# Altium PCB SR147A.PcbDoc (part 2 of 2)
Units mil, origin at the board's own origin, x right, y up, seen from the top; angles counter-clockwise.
Board outline 3000 x 3006 mil, 4 copper layers (Top Layer, Signal Layer 1, Signal Layer 2, Bottom Layer), stack 60.434 mil thick; 65 components, 14 nets, 93 pads, 851 vias.
Unrouted connection lines stored in the file: 2.
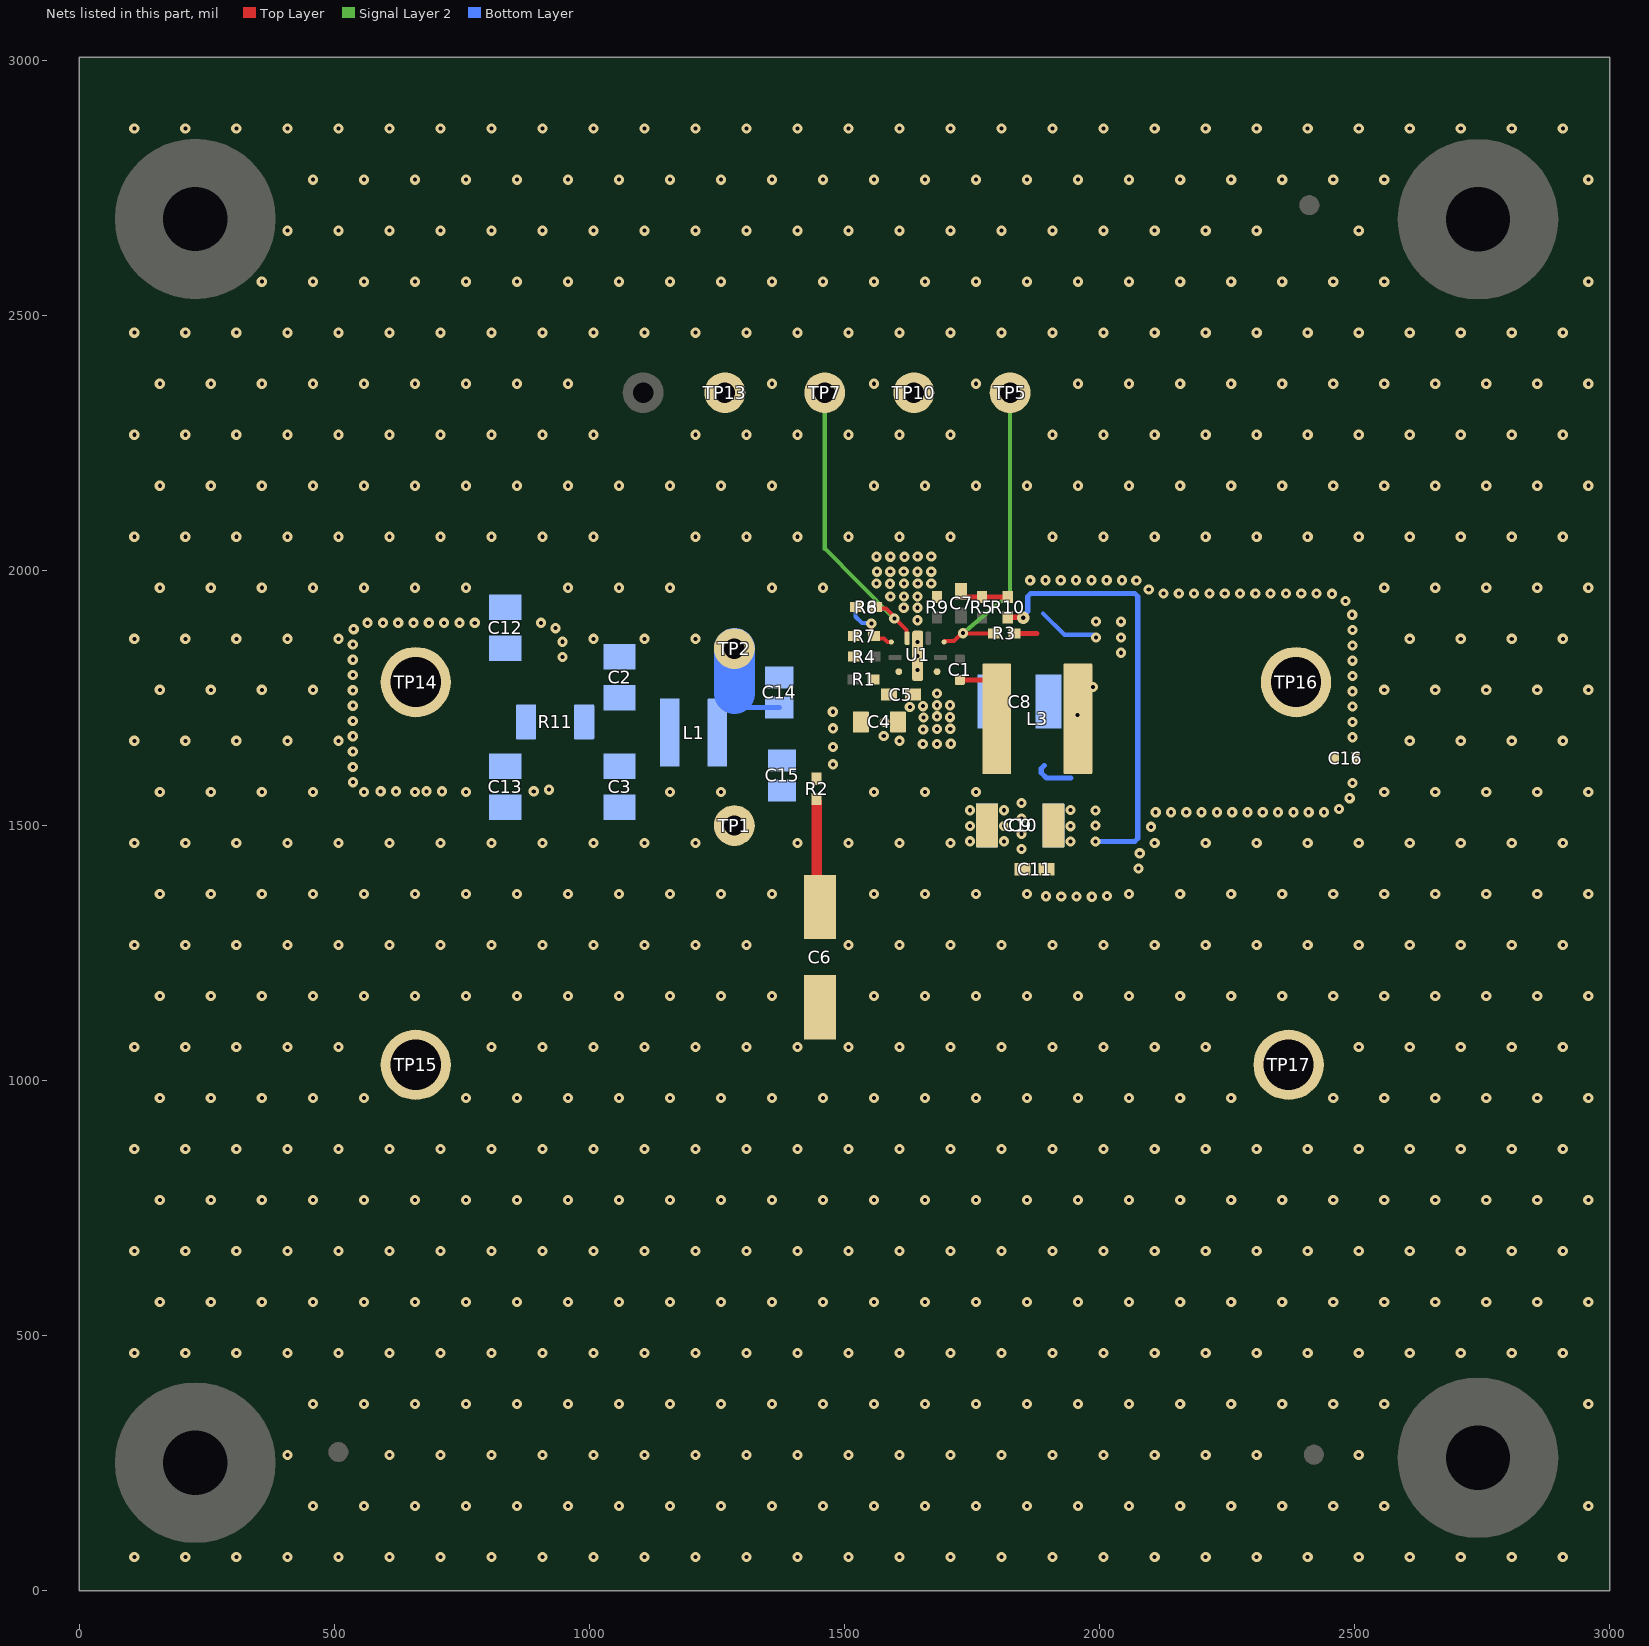
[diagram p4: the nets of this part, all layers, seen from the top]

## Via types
v1: diameter 20, hole 8, Top Layer to Bottom Layer, tented both sides, 847 vias
v2: diameter 19.68, hole 7.87, Top Layer to Bottom Layer, tented both sides, 3 vias
v3: diameter 24, hole 8, Top Layer to Bottom Layer, tented both sides, 1 vias

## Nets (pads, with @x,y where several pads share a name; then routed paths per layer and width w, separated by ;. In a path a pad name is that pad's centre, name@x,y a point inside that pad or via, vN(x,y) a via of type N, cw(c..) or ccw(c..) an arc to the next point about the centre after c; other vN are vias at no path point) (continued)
GND: C2.2 C3.2 C4.1 C5.2 C6.2 C8.2 C9.1 C10.1 C11.2 C12.2 C13.2 C14.2 C15.2 C16.2 R4.1 R7.1 R8.1 R9.1 TP1.1 TP10.1 TP13.1 TP15.1 TP17.1 U1.2
  other v1: 108,66 208,66 308,66 408,66 508,66 608,66 708,66 808,66 908,66 1008,66 1108,66 1208,66 1308,66 1408,66 1508,66 1608,66 1708,66 1808,66 1908,66 2008,66 2108,66 2208,66 2308,66 2408,66 2508,66 2608,66 2708,66 2808,66 2908,66 458,166 558,166 658,166 758,166 858,166 958,166 1058,166 1158,166 1258,166 1358,166 1458,166 1558,166 1658,166 1758,166 1858,166 1958,166 2058,166 2158,166 2258,166 2358,166 2458,166 2558,166 2958,166 408,266 608,266 708,266 808,266 908,266 1008,266 1108,266 1208,266 1308,266 1408,266 1508,266 1608,266 1708,266 1808,266 1908,266 2008,266 2108,266 2208,266 2308,266 2508,266 458,366 558,366 658,366 758,366 858,366 958,366 1058,366 1158,366 1258,366 1358,366 1458,366 1558,366 1658,366 1758,366 1858,366 1958,366 2058,366 2158,366 2258,366 2358,366 2458,366 2558,366 2958,366 108,466 208,466 308,466 408,466 508,466 608,466 708,466 808,466 908,466 1008,466 1108,466 1208,466 1308,466 1408,466 1508,466 1608,466 1708,466 1808,466 1908,466 2008,466 2108,466 2208,466 2308,466 2408,466 2508,466 2608,466 2708,466 2808,466 2908,466 158,566 258,566 358,566 458,566 558,566 658,566 758,566 858,566 958,566 1058,566 1158,566 1258,566 1358,566 1458,566 1558,566 1658,566 1758,566 1858,566 1958,566 2058,566 2158,566 2258,566 2358,566 2458,566 2558,566 2658,566 2758,566 2858,566 2958,566 108,666 208,666 308,666 408,666 508,666 608,666 708,666 808,666 908,666 1008,666 1108,666 1208,666 1308,666 1408,666 1508,666 1608,666 1708,666 1808,666 1908,666 2008,666 2108,666 2208,666 2308,666 2408,666 2508,666 2608,666 2708,666 2808,666 2908,666 158,766 258,766 358,766 458,766 558,766 658,766 758,766 858,766 958,766 1058,766 1158,766 1258,766 1358,766 1458,766 1558,766 1658,766 1758,766 1858,766 1958,766 2058,766 2158,766 2258,766 2358,766 2458,766 2558,766 2658,766 2758,766 2858,766 2958,766 108,866 208,866 308,866 408,866 508,866 608,866 708,866 808,866 908,866 1008,866 1108,866 1208,866 1308,866 1408,866 1508,866 1608,866 1708,866 1808,866 1908,866 2008,866 2108,866 2208,866 2308,866 2408,866 2508,866 2608,866 2708,866 2808,866 2908,866 158,966 258,966 358,966 458,966 558,966 758,966 858,966 958,966 1058,966 1158,966 1258,966 1358,966 1458,966 1558,966 1658,966 1758,966 1858,966 1958,966 2058,966 2158,966 2258,966 2458,966 2558,966 2658,966 2758,966 2858,966 2958,966 108,1066 208,1066 308,1066 408,1066 508,1066 808,1066 908,1066 1008,1066 1108,1066 1208,1066 1308,1066 1408,1066 1508,1066 1608,1066 1708,1066 1808,1066 1908,1066 2008,1066 2108,1066 2208,1066 2508,1066 2608,1066 2708,1066 2808,1066 2908,1066 158,1166 258,1166 358,1166 458,1166 558,1166 658,1166 758,1166 858,1166 958,1166 1058,1166 1158,1166 1258,1166 1358,1166 1558,1166 1658,1166 1758,1166 1858,1166 1958,1166 2058,1166 2158,1166 2258,1166 2358,1166 2458,1166 2558,1166 2658,1166 2758,1166 2858,1166 2958,1166 108,1266 208,1266 308,1266 408,1266 508,1266 608,1266 708,1266 808,1266 908,1266 1008,1266 1108,1266 1208,1266 1308,1266 1508,1266 1608,1266 1708,1266 1808,1266 1908,1266 2008,1266 2108,1266 2208,1266 2308,1266 2408,1266 2508,1266 2608,1266 2708,1266 2808,1266 2908,1266 1984.88,1360.44 1894.88,1361.42 1924.88,1361.09 1954.88,1360.76 2014.84,1361.86 158,1366 258,1366 358,1366 458,1366 558,1366 658,1366 758,1366 858,1366 958,1366 1058,1366 1158,1366 1258,1366 1358,1366 1558,1366 1658,1366 1758,1366 1858,1366 2058,1366 2158,1366 2258,1366 2358,1366 2458,1366 2558,1366 2658,1366 2758,1366 2858,1366 2958,1366 2076.53,1415.65 2078.77,1445.57 1847.24,1453.9 108,1466 208,1466 308,1466 408,1466 508,1466 608,1466 708,1466 808,1466 908,1466 1008,1466 1108,1466 1208,1466 1408,1466 1508,1466 1608,1466 1708,1466 2108,1466 2208,1466 2308,1466 2408,1466 2508,1466 2608,1466 2708,1466 2808,1466 2908,1466 1745.83,1469 1812.7,1469 1847.24,1483.9 2100.65,1497.5 1745.83,1498.87 1812.7,1499 1847.24,1513.9 2109.95,1526.02 2139.95,1526.02 2169.95,1526.02 2199.95,1526.02 2229.95,1526.02 2259.95,1526.02 2289.95,1526.02 2319.95,1526.02 2349.95,1526.02 2379.95,1526.02 2409.95,1526.02 2439.95,1526.11 1745.83,1530 1812.7,1530 2469.33,1532.2 1847.24,1543.9 2490.31,1553.65 158,1566 258,1566 358,1566 458,1566 558,1566 658,1566 758,1566 1158,1566 1258,1566 1558,1566 1658,1566 1758,1566 2558,1566 2658,1566 2758,1566 2858,1566 2958,1566 590.88,1567.03 620.88,1567.03 680.88,1567.03 710.88,1567.03 890.88,1567.03 920.7,1570.33 2495.91,1583.12 536.83,1584.97 536.35,1614.97 536.35,1644.97 1653.62,1659.84 1681.59,1659.84 1708.43,1660.26 108,1666 208,1666 308,1666 408,1666 508,1666 1608,1666 2608,1666 2708,1666 2808,1666 2908,1666 2495.91,1673.12 536.35,1674.97 1576.94,1675.25 1654.3,1688.21 1681.59,1689.47 1707.33,1689.61 1578.54,1702.97 2495.91,1703.12 536.35,1704.97 1654.7,1711.74 1706.73,1712.42 1681.59,1714.05 1628.11,1732.07 2495.91,1733.12 1654.16,1734 536.35,1734.97 1681.59,1735.79 1706.73,1735.79 1681.59,1758.54 2495.91,1763.12 536.35,1764.97 158,1766 258,1766 358,1766 458,1766 2558,1766 2658,1766 2758,1766 2858,1766 2958,1766 2495.91,1793.12 536.35,1794.97 2495.91,1823.12 536.35,1824.97 947.48,1830.21 2495.91,1853.12 536.35,1854.97 947.32,1860.21 108,1866 208,1866 308,1866 408,1866 508,1866 1008,1866 1108,1866 1208,1866 2608,1866 2708,1866 2808,1866 2908,1866 2495.91,1883.12 537.98,1884.93 933.4,1886.78 565.27,1897.39 595.27,1897.39 625.27,1897.39 655.27,1897.39 685.27,1897.39 715.27,1897.39 745.27,1897.39 775.27,1897.39 905.34,1897.39 1643.23,1902.44 2495.18,1913.11 1616.22,1926.87 1643.23,1926.87 2481.79,1939.95 1589.85,1949.14 1616.62,1949.1 1643.23,1949.1 2455.35,1954.12 2125.36,1954.92 2155.36,1954.92 2185.36,1954.92 2215.36,1954.92 2245.36,1954.92 2275.36,1954.92 2305.36,1954.92 2335.36,1954.92 2365.36,1954.92 2395.36,1954.92 2425.36,1954.92 2096.35,1962.56 158,1966 258,1966 358,1966 458,1966 558,1966 658,1966 758,1966 958,1966 1058,1966 1158,1966 1358,1966 1458,1966 2558,1966 2658,1966 2758,1966 2858,1966 2958,1966 1563.07,1974.35 1589.51,1973.97 1616.45,1974.35 1643.56,1974.35 1670.16,1974.35 2072.1,1980.22 1864,1980.61 1894,1980.84 1924,1980.84 1954,1980.84 1984,1980.84 2014,1980.84 2044,1980.84 1563.63,1997.6 1589.67,1997.6 1616.22,1998.1 1643.23,1997.6 1670.16,1997.6 1563.07,2027 1589.85,2027 1617.81,2026.71 1643.55,2027.49 1670.16,2027.49 108,2066 208,2066 308,2066 408,2066 508,2066 608,2066 708,2066 808,2066 908,2066 1008,2066 1208,2066 1308,2066 1408,2066 1508,2066 1608,2066 1708,2066 1908,2066 2008,2066 2108,2066 2208,2066 2308,2066 2408,2066 2508,2066 2608,2066 2708,2066 2808,2066 2908,2066 158,2166 258,2166 358,2166 458,2166 558,2166 658,2166 758,2166 858,2166 958,2166 1058,2166 1158,2166 1258,2166 1358,2166 1558,2166 1658,2166 1758,2166 1858,2166 1958,2166 2058,2166 2158,2166 2258,2166 2358,2166 2458,2166 2558,2166 2658,2166 2758,2166 2858,2166 2958,2166 108,2266 208,2266 308,2266 408,2266 508,2266 608,2266 708,2266 808,2266 908,2266 1008,2266 1208,2266 1308,2266 1408,2266 1508,2266 1608,2266 1708,2266 1908,2266 2008,2266 2108,2266 2208,2266 2308,2266 2408,2266 2508,2266 2608,2266 2708,2266 2808,2266 2908,2266 158,2366 258,2366 358,2366 458,2366 558,2366 658,2366 758,2366 858,2366 958,2366 1358,2366 1558,2366 1758,2366 1958,2366 2058,2366 2158,2366 2258,2366 2358,2366 2458,2366 2558,2366 2658,2366 2758,2366 2858,2366 2958,2366 108,2466 208,2466 308,2466 408,2466 508,2466 608,2466 708,2466 808,2466 908,2466 1008,2466 1108,2466 1208,2466 1308,2466 1408,2466 1508,2466 1608,2466 1708,2466 1808,2466 1908,2466 2008,2466 2108,2466 2208,2466 2308,2466 2408,2466 2508,2466 2608,2466 2708,2466 2808,2466 2908,2466 358,2566 458,2566 558,2566 658,2566 758,2566 858,2566 958,2566 1058,2566 1158,2566 1258,2566 1358,2566 1458,2566 1558,2566 1658,2566 1758,2566 1858,2566 1958,2566 2058,2566 2158,2566 2258,2566 2358,2566 2458,2566 2558,2566 2958,2566 408,2666 508,2666 608,2666 708,2666 808,2666 908,2666 1008,2666 1108,2666 1208,2666 1308,2666 1408,2666 1508,2666 1608,2666 1708,2666 1808,2666 1908,2666 2008,2666 2108,2666 2208,2666 2308,2666 2508,2666 458,2766 558,2766 658,2766 758,2766 858,2766 958,2766 1058,2766 1158,2766 1258,2766 1358,2766 1458,2766 1558,2766 1658,2766 1758,2766 1858,2766 1958,2766 2058,2766 2158,2766 2258,2766 2358,2766 2458,2766 2558,2766 2958,2766 108,2866 208,2866 308,2866 408,2866 508,2866 608,2866 708,2866 808,2866 908,2866 1008,2866 1108,2866 1208,2866 1308,2866 1408,2866 1508,2866 1608,2866 1708,2866 1808,2866 1908,2866 2008,2866 2108,2866 2208,2866 2308,2866 2408,2866 2508,2866 2608,2866 2708,2866 2808,2866 2908,2866
  other v2: 1643.56,1805.05 1643.56,1832.61 1643.56,1860.17
MODE/SYNC: R6.2 R8.2 TP7.1 U1.7 | length 661.6
  Top Layer w8: R8.2@1562.11,1928.12 1564.69,1925.55 1581.24,1925.55 1597.73,1909.05 v1(1597.73,1905.93) 1599.08,1905.93 1621.97,1883.03 1621.97,1867.98 U1.7@1622.9,1867.06
  Signal Layer 2 w8: 1461.3,2042.17 TP7.1@1461.3,2367 ; 1461.3,2044 1597.3,1905.93 v1(1597.73,1905.93)
  Bottom Layer w8: R6.2@1562.11,1927.92 1565.65,1924.39 1581.2,1924.39 1597.73,1907.86 v1(1597.73,1905.93)
NetC2_1: C2.1 C3.1 L1.1 R11.2
NetC6_1: C6.1 R2.1 | length 158.2
  Top Layer w20: R2.1@1445.44,1547.32 1445.6,1547.16 1445.6,1389.36 C6.1@1445.74,1389.23
NetC7_1: C7.1 R5.2 R10.1 | length 95
  Top Layer w10: C7.1@1725.08,1947.61 R5.2@1769.16,1947.61 R10.1@1820.07,1947.61
NetC12_1: C12.1 C13.1 R11.1 TP14.1
PGOOD: R3.2 TP5.1 U1.5 | length 613.7
  Top Layer w8: U1.5@1695.24,1859.68 1696.89,1861.33 1714.77,1861.33 1730.44,1877 v1(1732.61,1877) ; v1@1733.2,1876.41 R3.2@1793.1,1876.41
  Signal Layer 2 w8: v1(1732.61,1877) 1824.61,1955.04 TP5.1@1824.61,2342.83
  Bottom Layer w8: v1(1732.61,1877) v1@1733.2,1876.41
RT: R6.1 R7.2 U1.8 | length 113.1
  Top Layer w8: v1@1552.62,1892.29 1552.62,1866.57 R7.2@1553,1866.19 ; R7.2@1563.07,1867.37 1563.63,1866.8 1577.22,1866.8 1584.19,1859.84 1591.73,1859.84 U1.8@1591.89,1859.68
  Bottom Layer w8: R6.1@1522.74,1927.92 1521.81,1926.99 1521.81,1909.25 1534.48,1896.58 v1@1552.34,1896.58
  other v1: 1552.62,1896.29
SW: C1.2 L3.1 U1.3 | length 87.2
  Top Layer w10: C1.2@1726.01,1785.37 1786.71,1785.37 1801.01,1771.08 L3.1@1801.01,1764.76
VIN: C4.2 C5.1 C14.1 C15.1 L1.2 R1.2 R2.2 TP2.1 U1.1 | length 187.5
  Bottom Layer w10: 1284.16,1758.52 1311.21,1731.47 C14.1@1372.16,1731.47
  Bottom Layer w80: 1284.16,1758.52 TP2.1@1284.16,1846.84
  other v1: 1477.61,1620 1477.61,1654 1477.61,1690.5 1477.16,1723
VOUT: C8.1 C9.2 C10.2 C11.1 C16.1 L3.2 R3.1 R10.2 TP16.1 | length 1089.4
  Top Layer w10: R10.2@1820.07,1908.24 1850.46,1908.24 v3(1850.46,1907.34) ; R3.1@1832.85,1876.41 1877.21,1876.41
  Bottom Layer w8: 1889.19,1915.68 1930.92,1873.95 v1@1988.16,1873.95
  Bottom Layer w10: v3(1850.46,1907.34) 1850.46,1911.13 1859.29,1919.96 1859.29,1949.18 1865.14,1955.04 2068.99,1955.04 2074.85,1949.18 2074.85,1474.86 2068.99,1469 v1@1999.37,1469 ; 1891.61,1617.53 1885.75,1611.67 1885.75,1603.39 1896.19,1592.95 1944.16,1592.95
  other v1: 1943.13,1468.68 1992.13,1468.53 1943.13,1498.68 1992.13,1499.94 1943.13,1530.48 1992.13,1529.53 1956.99,1716.56 1987.13,1771.48 2042.13,1838.6 1993.13,1868.75 2042.13,1868.6 1993.13,1899.75 2042.13,1899.6
pads on no net: FID1.1 FID2.1 FID3.1 FID4.1 FID5.1 FID6.1 H1.1 H2.1 H3.1 H4.1 H5.0 H6.0 H7.0 H8.0 LBL1.0

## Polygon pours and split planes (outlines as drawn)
GND on Top Layer "TOP_LAYER_GND_P230" (solid, remove dead copper, pour order 230): 6,3006 0,3000 2,2 2000,2 2002,4 3000,0 3000,3000
VIN on Top Layer "TOP_LAYER_VIN_P214" (solid, remove dead copper, pour order 214): 1614.55,1809.37 1614.55,1785.28 1602.23,1772.96 1602.23,1733.06 1573.92,1733.06 1552.62,1711.76 1552.62,1671.1 1519.76,1638.25 1519.76,1577.06 1434.35,1577.06 1434.35,1709.11 1534.62,1809.37
SW on Top Layer "TOP_LAYER_SW_P213" (solid, remove dead copper, pour order 213): 1671.7,1808.69 1672.01,1809 1699.91,1809 1703.58,1805.33 1748.22,1805.89 1760.39,1818.06 1826.6,1818.06 1826.6,1601.15 1768.98,1601.15 1768.98,1700.8 1692.56,1777.21 1676.71,1777.21 1671.38,1782.61
VOUT on Top Layer "TOP_LAYER_VOUT_P225" (solid, remove dead copper, pour order 225): 1900.99,1385.03 1990.94,1385.03 ccw(c1991.02,1422.7) 2028.7,1422.7 2028.7,1490.92 cw(c2084.3,1490.92) 2084.3,1546.53 2445.84,1546.53 ccw(c2445.84,1575.83) 2475.13,1575.83 2475.13,1905.92 ccw(c2446.53,1905.92) 2446.53,1934.53 1903.85,1934.53 ccw(c1903.85,1900.81) 1870.14,1900.81 1870.14,1415.88 ccw(c1900.99,1415.88)
NetC2_1 on Bottom Layer "BOTTOM_LAYER_NETC2_1_P224" (solid, remove dead copper, pour order 224): 965.05,1587.43 1158.44,1587.43 ccw(c1158.44,1610.69) 1181.7,1610.69 1181.7,1766.08 ccw(c1166.65,1766.08) 1166.65,1781.12 961.72,1781.12 ccw(c961.72,1768.32) 948.92,1768.33 948.75,1603.74 ccw(c965.05,1603.72)
VOUT on Bottom Layer "BOTTOM_LAYER_VOUT_P221" (solid, remove dead copper, pour order 221): 1908.82,1385.03 2025.16,1385.03 ccw(c2025.16,1416.01) 2056.13,1416.01 2056.13,1920.27 ccw(c2035.88,1920.27) 2035.88,1940.53 1897.74,1940.53 ccw(c1897.74,1921.6) 1878.81,1921.64 1877.73,1416.18 ccw(c1908.82,1416.12)
NetC12_1 on Bottom Layer "BOTTOM_LAYER_NETC12_1_P220" (solid, remove dead copper, pour order 220): 556.74,1587.43 556.74,1877 905.34,1877 cw(c905.34,1855.26) 927.09,1855.26 927.09,1610.39 cw(c904.12,1610.39) 904.12,1587.43
VIN on Bottom Layer "BOTTOM_LAYER_VIN_P222" (solid, remove dead copper, pour order 222): 1268.16,1606 1223.6,1606 cw(c1223.6,1625.44) 1204.16,1625.44 1204.16,1739.97 cw(c1222.73,1739.97) 1222.73,1758.54 1476.62,1758.54 cw(c1476.62,1741) 1494.16,1740.99 1494.16,1622.34 cw(c1477.82,1622.34) 1477.82,1606
GND on Bottom Layer "BOTTOM_LAYER_GND_P233" (solid, remove dead copper, pour order 233): 4,3006 4,-2 10,4 3000,4 3000,3002.99
VOUT on Signal Layer 2 "SIGNAL_LAYER_2_VOUT_P218" (solid, remove dead copper, pour order 218): 1867.63,1405.71 1867.63,1910.45 cw(c1893.72,1910.45) 1893.72,1936.53 1992.63,1936.53 1990.63,1934.53 2445.98,1934.53 cw(c2445.98,1904.98) 2475.52,1904.98 2475.52,1584.31 cw(c2437.62,1584.31) 2437.62,1546.41 2101.2,1546.41 ccw(c2101.2,1476.35) 2031.13,1476.35 2031.13,1409.42 cw(c2002.36,1409.42) 2002.05,1380.64 1891.23,1381.85 cw(c1891.49,1405.71)
GND on Signal Layer 2 "SIGNAL_LAYER_2_GND_P232" (solid, remove dead copper, pour order 232): 4,3006 4,-2 3000,-2 3000,3002.99
GND on Signal Layer 1 "SIGNAL_LAYER_1_GND_P231" (solid, remove dead copper, pour order 231): 0,3006 0,2 2,0 4,2 3000,2 3000,2996.98

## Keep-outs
Keep-Out Layer:
  lines w10: 0,0 0,3002 3000,3002 3000,0 0,0
  text ".Layer_Name" at 577,-858.49 h60

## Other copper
Top Layer:
  text ".Layer_Name" at 577,-858.49 h60
Signal Layer 1:
  text ".Layer_Name" at 581,-861 h60
Signal Layer 2:
  text ".Layer_Name" at 581,-860 h60
Bottom Layer:
  pour cut-out: 949.52,1579.89 927.09,1579.89 927.09,1790.53 949.52,1790.53
  pour cut-out: 1204.16,1597.84 1181.7,1597.84 1181.7,1766.08 1182.32,1766.7 1204.16,1766.7
  text ".Layer_Name" at 577,-858.49 h60

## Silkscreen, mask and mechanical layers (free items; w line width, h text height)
Top Overlay:
  lines w3.94: 1497.97,1386.95 2020.57,1386.95 2020.57,1984.62 1497.97,1984.62 1497.97,1386.95
  text "GND" at 1207.12,2248 h35
  text "EN" at 1052.61,2246 h35
  text "MODE" at 1378.16,2246 h35
  text "GND" at 1587.24,2246 h35
  text "PGOOD" at 1740.16,2246 h35
  text "SYNC" at 1378.16,2188 h35
  text "VOUT+" at 2101.4,1808.41 h40
  text "VIN_EMI+" at 227.5,1790.53 h40
  text "CAUTION:" at 878.82,1742.43 h30
  text "VINS" at 1224.47,1728.2 h35
  text "HOT SURFACE" at 833.51,1694.21 h30
  text "GND" at 1228.16,1388 h35
  text "13mm x 15.1mm" at 1569.76,1347 h30
  text "GND" at 393.52,1031.05 h40
  text "GND" at 2137.32,1031.05 h40
  text "'.PRJ_Number'.PCB_Rev" at 1390.47,733.92 h100
  text "LMR60460QEVM" at 1282,585 h80
  text ".Layer_Name" at 577,-858.49 h60
Bottom Overlay:
  text ".Layer_Name" at 577,-858.49 h60
Top Paste:
  text ".Layer_Name" at 577,-858.49 h60
Bottom Paste:
  text ".Layer_Name" at 577,-858.49 h60
Top Solder:
  text ".Layer_Name" at 577,-858.49 h60
  text ".Layer_Name" at 577,-858.49 h60
Bottom Solder:
  text ".Layer_Name" at 577,-858.49 h60
Drill Guide:
  text ".Layer_Name" at 577,-858.49 h60
M1 Board Outline:
  lines w10: 0,0 0,3000 3000,3000 3000,0 0,0
  text ".Layer_Name" at 577,-858.49 h60
M2 Board Dimensions:
  rectangle: 125,-400 500,-275
  rectangle: 0,-275 125,-150
  lines w7: 0,-275 1000,-275 ; 125,-400 125,-150 ; 250,-400 250,-150 ; 500,-400 500,-150 ; 750,-400 750,-150 ; 0,-400 0,-150 1000,-150 1000,-400 0,-400
  text ".Layer_Name" at 577,-858.49 h60
M3 3D STEP Top:
  text ".Layer_Name" at 577,-858.49 h60
M4 3D STEP Bottom:
  text ".Layer_Name" at 577,-858.49 h60
M5 Assembly Top:
  lines w10: -292,-930.17 6308,-930.17 ; -292,-726.83 6310,-726.83 ; -292,-523.5 -292,-1133.5 3713,-1133.5 6310,-1133.5 6310,-523.5 -291.5,-523.5 -291.5,-1133.5 1284,-1133.5 ; 2173,-1133.5 2173,-523.5 ; 3440,-726.83 3440,-523.5 ; 4280,-726.83 4280,-523.5 ; 4902,-1140 4902,-937.17
  text "COMPONENTS MARKED 'DNP' SHOULD NOT BE POPULATED." at 1153.5,-318.5 h60
  text "ASSEMBLY VARIANT:" at 1153,-434 h60
  text ".VariantName" at 2189,-434 h60
  text "PCB VIEWED FROM TOP SIDE" at -228.5,-655.67 h60
  text "BOARD #:" at 2248,-655.67 h60
  text ".PRJ_Number" at 2793.5,-655.67 h60
  text "REV:" at 3638,-655.67 h60
  text ".PCB_Rev" at 3929.5,-655.67 h60
  text "SVN REV:" at 4476,-655.67 h60
  text ".VersionControl_RevNumber" at 4982,-655.67 h60
  text "TID #:" at 2248,-859 h60
  text ".TID" at 2793.5,-859 h60
  text "PLOT NAME =" at -228.5,-1064.34 h60
  text ".plot_File_Name" at 577,-1064.34 h60
  text "GENERATED    :" at 2250,-1064.34 h60
  text ".Print_Date" at 3119.5,-1064.34 h60
  text ".Print_Time" at 3848.5,-1064.34 h60
  text "TEXAS INSTRUMENTS" at 5113,-1064.34 h60
M6 Assembly Bottom:
  lines w10: -292.5,-727.33 6309.5,-727.33 ; -290.5,-930.67 6309.5,-930.67 ; 1115.5,-1140.5 1115.5,-937.67 ; 1737.5,-727.33 1737.5,-524 ; 2577.5,-727.33 2577.5,-524 ; 3844.5,-1134 3844.5,-524 ; 4733.5,-1134 6309,-1134 6309,-524 -292.5,-524 -292.5,-1134 2304.5,-1134 6309.5,-1134 6309.5,-524
  text "COMPONENTS MARKED 'DNP' SHOULD NOT BE POPULATED." at 6102,-318 h60
  text ".VariantName" at 5058,-434 h60
  text "ASSEMBLY VARIANT:" at 6097,-434 h60
  text ".VersionControl_RevNumber" at 1035.5,-656.17 h60
  text "SVN REV:" at 1541.5,-656.17 h60
  text ".PCB_Rev" at 2088,-656.17 h60
  text "REV:" at 2379.5,-656.17 h60
  text ".PRJ_Number" at 3224,-656.17 h60
  text "BOARD #:" at 3769.5,-656.17 h60
  text "PCB VIEWED FROM BOTTOM SIDE" at 6246,-656.17 h60
  text ".TID" at 3224,-859.5 h60
  text "TID #:" at 3769.5,-859.5 h60
  text "TEXAS INSTRUMENTS" at 904.5,-1064.84 h60
  text ".Print_Time" at 2169,-1064.84 h60
  text ".Print_Date" at 2898,-1064.84 h60
  text "GENERATED    :" at 3767.5,-1064.84 h60
  text ".plot_File_Name" at 5440.5,-1064.84 h60
  text "PLOT NAME =" at 6246,-1064.84 h60
M9 Title Sheet:
  drawing of 57 lines, arcs and shapes, not listed
  text "1" at 739.84,8036.5 h70
  text "2" at 3235.5,8036.5 h70
  text "3" at 5724.84,8036.5 h70
  text "4" at 8231.51,8036.5 h70
  text "5" at 10730.5,8036.5 h70
  text "6" at 13235.5,8036.5 h70
  text "A" at -416.5,6893.5 h70
  text "A" at 14383.5,6893.5 h70
  text "B" at -416.5,4513.5 h70
  text "B" at 14383.5,4513.5 h70
  text "C" at -416.5,2138.5 h70
  text "C" at 14383.5,2138.5 h70
  text "PROJECT TITLE:" at 11343.5,277.5 h45
  text ".PRJ_Title" at 11393.5,144.17 h70
  text "DESIGNED FOR:" at 11343.5,-23.5 h45
  text ".PRJ_Customer" at 11393.5,-163.5 h70
  text "D" at -416.5,-231.5 h70
  text "D" at 14383.5,-231.5 h70
  text "FILE NAME:" at 11343.5,-323.5 h45
  text ".PCB_File_Name_No_Path" at 11393.5,-443.5 h70
  text "Texas Instruments (TI) and/or its licensors do not warrant the accuracy or completeness of this specification" at 6374,-605.34 h45
  text "ENGINEER:" at 11343.5,-613.5 h45
  text "LAYOUT BY:" at 12848.5,-613.5 h45
  text "or any information contained therein. TI and/or its licensors do not warrant that this design will meet" at 6329.01,-718 h45
  text ".PRJ_Engineer" at 11393.5,-768.49 h70
  text ".PCB_Layout" at 12899,-768.49 h70
  text "the specifications, will be suitable for your application or fit for any particular purpose, or will operate in" at 6329.01,-830.67 h45
  text ".Layer_Name" at 577,-858.49 h60
  text "ALTIUM DESIGNER VERSION:" at 12848.5,-923.5 h45
  text "an implementation. TI and/or its licensors do not warrant that the design is production worthy. You should" at 6329.01,-943.33 h45
  text "completely validate and test your design implementation to confirm the system functionality for your application." at 6374,-1056 h45
  text ".print_Scale" at 11393.5,-1056.83 h70
  text ".Application_BuildNumber" at 12899,-1056.83 h70
  text "1" at 739.84,-1263.5 h70
  text "2" at 3235.5,-1263.5 h70
  text "3" at 5724.84,-1263.5 h70
  text "4" at 8231.51,-1263.5 h70
  text "5" at 10730.5,-1263.5 h70
  text "6" at 13235.5,-1263.5 h70
M10 Fab Notes:
  drawing of 189 lines, arcs and shapes, not listed
  text "DESIGN INFORMATION" at 12382.02,6356.17 h60
  text "MIN. TRACK WIDTH:" at 11737.46,6224.05 h60
  text "8" at 12833.7,6224.05 h60
  text "MIL" at 12988.46,6224.05 h60
  text "MIN. CLEARANCE:" at 11737.46,6099.92 h60
  text "0.2" at 12773.7,6099.93 h60
  text "mm" at 12988.46,6099.92 h60
  text "MIN. VIA PAD SIZE:" at 11737.46,5975.8 h60
  text "24" at 12803.71,5975.8 h60
  text "MIL" at 12988.46,5975.8 h60
  text "0.05mm (2MIL)" at 12432.46,5845.9 h60
  text "MINIMUM ANNULAR RING" at 11408.23,5837.67 h60
  text "EXTERNAL" at 13140.46,5837.67 h60
  text "PER" at 11608.23,5727.55 h60
  text "IPC-D-275 CLASS 2 LEVEL C" at 11828.23,5727.54 h60
  text "MIL, HOLES" at 13316.46,5627.07 h60
  text "+/-" at 12924,5618.48 h60
  text "+/-" at 13778,5618.48 h60
  text "REGISTRATION TOLERANCES:" at 11408.23,5617.42 h60
  text "METAL" at 12608,5617.42 h60
  text "5" at 13184.2,5617.42 h60
  text "3" at 14017.2,5617.42 h60
  text "MIL" at 14133.46,5617.42 h60
  text "HOLE SIZE TOLERANCE (UNLESS OTHERWISE SPECIFIED):" at 11408.23,5519.1 h60
  text "+/-" at 13778,5516.23 h60
  text "3" at 14017.2,5515.17 h60
  text "MIL" at 14133.46,5515.17 h60
  text "MATERIAL:" at 11333.46,5377.52 h60
  text "FR-4 High Tg" at 12319.9,5249 h60
  text "X" at 12175.46,5241.01 h60
  text "FR-408" at 11754.46,5236.49 h60
  text "OTHER" at 13242.46,5236.49 h60
  text "62 MIL (1.6mm) +/-10%" at 12074.56,5093.46 h60
  text "X" at 11954.46,5091.01 h60
  text "THICKNESS:" at 11408.23,5085.24 h60
  text "OTHER" at 13359.46,5085.24 h60
  text "TOLERANCE:" at 11408.23,4946.92 h60
  text "X" at 12256.46,4946.92 h60
  text "ANSI IPC-6012 TYPE 3 CLASS 2" at 12434.48,4946.92 h60
  text "OTHER +/-" at 12434.46,4802.73 h60
  text "BOW & TWIST:" at 11408.23,4657.54 h60
  text "X" at 12256.46,4657.54 h60
  text "ANSI IPC-6012 TYPE 3 CLASS 2" at 12434.48,4657.54 h60
  text "OTHER +/-" at 12434.46,4510.85 h60
  text "DRILLING:" at 11333.46,4380.23 h60
  text "NC_DRILL FILES" at 13094.46,4275.04 h60
  text "REFERENCE:" at 11408.23,4271.1 h60
  text "X" at 12065.46,4271.01 h60
  text "AS SHOWN" at 12243.46,4271.1 h60
  text "X" at 12966.46,4271.1 h60
  text "OTHER" at 13392.46,4128.85 h60
  text "PTH COPPER THICKNESS:" at 11407.91,4125.32 h60
  text "X" at 12547.14,4125.32 h60
  text "20-30 um" at 12675.14,4125.32 h60
  text "BOARD FINISH:" at 11333.46,3977.73 h60
  text "SILKSCREEN:" at 11488.68,3867.6 h60
  text "X" at 12446.46,3867.6 h60
  text "TOP" at 12563.46,3867.6 h60
  text "X" at 12956.46,3867.6 h60
  text "BOTTOM" at 13074.46,3867.6 h60
  text "SILKSCREEN COLOR:" at 11488.68,3712.41 h60
  text "X" at 12445.46,3712.41 h60
  text "WHITE" at 12563.46,3712.41 h60
  text "OTHER" at 13074.46,3712.41 h60
  text "X" at 12576.46,3568.96 h60
  text "GREEN" at 12694.46,3568.96 h60
  text "OTHER" at 13312.46,3568.96 h60
  text "SOLDER RESIST COLOR:" at 11488.68,3562.1 h60
  text "X" at 12576.46,3414.71 h60
  text "MATTE" at 12694.46,3414.71 h60
  text "SEMI-GLOSS" at 13312,3414.07 h60
  text "IMMERSION GOLD (ENIG)" at 12394.46,3241.94 h60
  text "ENEPIG" at 13732,3234.72 h60
  text "SURFACE FINISH:" at 11333.46,3233.72 h60
  text "X" at 12216.46,3233.72 h60
  text "IMM. TIN/SILVER OR EQUIV" at 11663,3096.4 h60
  text "OTHER" at 13094.46,3092.47 h60
  text "ARRAY/PANEL:" at 11333.46,2937.09 h60
  text "CUT AND TRIM PER M1 BOARD OUTLINE" at 12394.46,2928.87 h60
  text "N.C. ROUTE" at 12394.46,2792.9 h60
  text "X" at 13082.46,2792.9 h60
  text "V. SCORE" at 13260.46,2792.9 h60
  text "CERTIFICATION:" at 11333.46,2663.77 h60
  text "MATERIALS AND WORKMANSHIP FOR ALL PCBS" at 12058.46,2663.77 h60
  text "TO MEET OR EXCEED THE REQUIREMENTS OF:" at 12058.46,2569.71 h60
  text "X" at 11695.97,2441.08 h60
  text "ANSI IPC-A-600F CLASS ->" at 11823.96,2441.08 h60
  text "X" at 13471.97,2441.08 h60
  text "2" at 13581.96,2441.08 h60
  text "1" at 13266.96,2439.58 h60
  text "3" at 13935.96,2439.58 h60
  text "X" at 12507.97,2293.39 h60
  text "RoHS" at 12635.96,2293.39 h60
  text "OTHER" at 13280.36,2293.39 h60
  text "PER ORDER" at 13677.42,2293.39 h60
  text "ALL BOARDS MUST MEET OR EXCEED UL94-V0 REQUIREMENTS." at 11361,2139.57 h60
  text "PCB MUST BEAR THE UL94V-0 UL REGISTERED MATERIAL ID NUMBER" at 11361,2023.5 h60
  text "ADDITIONAL REQUIREMENTS:" at 11333.46,1854.08 h60
  text "MICROSECTION:" at 11408.23,1746.95 h60
  text "YES" at 12313.96,1746.95 h60
  text "REQUIRED" at 13175.46,1602.62 h60
  text "BARE BOARD ELEC. TEST:" at 11408.23,1599.76 h60
  text "NONE" at 12713.96,1599.76 h60
  text "X" at 13057.46,1599.76 h60
  text "PER ORDER" at 13767.46,1599.76 h60
  text "XX MIL VIAS REQUIRE NON-CONDUCTIVE FILL AND PLANARIZE" at 11576.38,1394.82 h59
  text "XX MIL VIAS REQUIRE CONDUCTIVE FILL AND PLANARIZE" at 11584.38,1290.84 h60
  text "OUTER XX MIL TRACES REQUIRE 50 OHM SINGLE-ENDED IMPEDANCE" at 11583.39,1127.46 h58
  text "LAYER 2 & 3 (INNER LAYERS) XX MIL WIDE, XX MIL SPACE / TRACES REQUIRE 100 OHM DIFFERENTIAL IMPEDANCE" at 11575.39,891.74 h60
  text ".Layer_Name" at 577,-858.49 h60
M11 Gerber Information:
  lines w10: -292,-930.17 6308,-930.17 ; -292,-726.83 6310,-726.83 ; -292,-523.5 -292,-1133.5 3713,-1133.5 6310,-1133.5 6310,-523.5 -291.5,-523.5 -291.5,-1133.5 1284,-1133.5 ; 2173,-1133.5 2173,-523.5 ; 3440,-726.83 3440,-523.5 ; 4280,-726.83 4280,-523.5 ; 4902,-1140 4902,-937.17
  text "ALL ARTWORK VIEWED FROM TOP SIDE" at -228.5,-655.67 h60
  text "BOARD #:" at 2248,-655.67 h60
  text ".PRJ_Number" at 2793.5,-655.67 h60
  text "REV:" at 3638,-655.67 h60
  text ".PCB_Rev" at 3929.5,-655.67 h60
  text "SVN REV:" at 4476,-655.67 h60
  text ".VersionControl_RevNumber" at 4982,-655.67 h60
  text "LAYER NAME =" at -228.5,-858.49 h60
  text "TID #:" at 2248,-859 h60
  text ".TID" at 2793.5,-859 h60
  text "PLOT NAME =" at -228.5,-1064.34 h60
  text ".plot_File_Name" at 577,-1064.34 h60
  text "GENERATED    :" at 2250,-1064.34 h60
  text ".Print_Date" at 3119.5,-1064.34 h60
  text ".Print_Time" at 3848.5,-1064.34 h60
  text "TEXAS INSTRUMENTS" at 5113,-1064.34 h60
M12 Stackup:
  drawing of 295 lines, arcs and shapes, not listed
  text "Layer" at 9820.35,7845 h60
  text "Name" at 10230.26,7845 h60
  text "Material" at 11170,7845 h60
  text "Thickness" at 12029.77,7845 h60
  text "Constant" at 12679.6,7845 h60
  text "Board Layer Stack" at 13249.46,7845 h60
  text "Top Overlay" at 10230.26,7725 h60
  text "Top Solder" at 10230.26,7605 h60
  text "Solder Resist" at 11170,7605 h60
  text "0.40mil" at 12029.77,7605 h60
  text "3.5" at 12679.6,7605 h60
  text "1" at 9820.35,7485 h60
  text "Top Layer" at 10230.26,7485 h60
  text "2.80mil" at 12029.77,7485 h60
  text "Dielectric 1" at 10230.26,7365 h60
  text "FR-4 High Tg" at 11170,7365 h60
  text "10.00mil" at 12029.77,7365 h60
  text "4.2" at 12679.6,7365 h60
  text "2" at 9820.35,7245 h60
  text "Signal Layer 1" at 10230.26,7245 h60
  text "1.42mil" at 12029.77,7245 h60
  text "Dielectric2" at 10230.26,7125 h60
  text "FR-4 High Tg" at 11170,7125 h60
  text "32.00mil" at 12029.77,7125 h60
  text "4.2" at 12679.6,7125 h60
  text "3" at 9820.35,7005 h60
  text "Signal Layer 2" at 10230.26,7005 h60
  text "1.42mil" at 12029.77,7005 h60
  text "Dielectric 3" at 10230.26,6885 h60
  text "FR-4 High Tg" at 11170,6885 h60
  text "10.00mil" at 12029.77,6885 h60
  text "4.2" at 12679.6,6885 h60
  text "4" at 9820.35,6765 h60
  text "Bottom Layer" at 10230.26,6765 h60
  text "2.80mil" at 12029.77,6765 h60
  text "Bottom Solder" at 10230.26,6645 h60
  text "Solder Resist" at 11170,6645 h60
  text "0.40mil" at 12029.77,6645 h60
  text "3.5" at 12679.6,6645 h60
  text "Bottom Overlay" at 10230.26,6525 h60
  text "Total board thickness:" at 9820.35,6405 h60
  text "61.23mil" at 12029.77,6405 h60
  text ".Layer_Name" at 577,-858.49 h60
M13 Component Bodies Top:
  text ".Layer_Name" at 577,-858.49 h60
M14 Component Bodies Bottom:
  text ".Layer_Name" at 577,-858.49 h60
M15 Courtyards Top:
  text ".Layer_Name" at 577,-858.49 h60
M16 Courtyards Bottom:
  text ".Layer_Name" at 577,-858.49 h60
Drill Drawing:
  circle w10: c5863.72,3073.32 r27.63
  lines w10: 5836.09,2921.38 5891.34,2921.38 5891.34,2976.63 5836.09,2976.63 5836.09,2921.38 ; 5836.09,3170.02 5863.72,3183.83 5891.34,3170.02 5877.53,3197.64 5891.34,3225.27 5863.72,3211.46 5836.09,3225.27 5849.9,3197.64 5836.09,3170.02 ; 5836.09,3349.59 5891.34,3349.59 5863.72,3294.34 5836.09,3349.59 ; 5836.09,3432.47 5849.9,3432.47 5863.72,3418.66 5877.53,3432.47 5891.34,3432.47 5877.53,3446.28 5891.34,3460.1 5877.53,3460.1 5863.72,3473.91 5849.9,3460.1 5836.09,3460.1 5849.9,3446.28 5836.09,3432.47
  lines w12: 5786,2884.08 9017.49,2884.08 ; 5786,3505.68 9017.49,3505.68 ; 6123.86,2759.76 6123.86,3630 ; 6455.86,2759.76 6455.86,3630 ; 7092.43,2759.76 7092.43,3630 ; 7351.57,2759.76 7351.57,3630 ; 7726.72,2759.76 7726.72,3630 ; 8451.05,2759.76 8451.05,3630 ; 5786,2759.76 9017.49,2759.76 9017.49,3630 5786,3630 5786,2759.76
  text "Symbol" at 5860.59,3542.98 h72
  text "Quantity" at 6161.16,3542.98 h72
  text "Finished Hole Size" at 6493.16,3542.98 h72
  text "Plated" at 7129.72,3542.98 h72
  text "Hole Type" at 7388.86,3542.98 h72
  text "Drill Layer Pair" at 7764.02,3542.98 h72
  text "Hole Tolerance" at 8488.35,3542.98 h72
  text "3" at 6161.16,3418.66 h60
  text "7.87mil (0.200mm)" at 6493.16,3418.66 h60
  text "PTH" at 7129.72,3418.66 h60
  text "Round" at 7388.86,3418.66 h60
  text "Top Layer - Bottom Layer" at 7764.02,3418.66 h60
  text "848" at 6161.16,3294.34 h60
  text "8.00mil (0.203mm)" at 6493.16,3294.34 h60
  text "PTH" at 7129.72,3294.34 h60
  text "Round" at 7388.86,3294.34 h60
  text "Top Layer - Bottom Layer" at 7764.02,3294.34 h60
  text "7" at 6161.16,3170.02 h60
  text "40.00mil (1.016mm)" at 6493.16,3170.02 h60
  text "PTH" at 7129.72,3170.02 h60
  text "Round" at 7388.86,3170.02 h60
  text "Top Layer - Bottom Layer" at 7764.02,3170.02 h60
  text "4" at 6161.16,3045.7 h60
  text "98.43mil (2.500mm)" at 6493.16,3045.7 h60
  text "PTH" at 7129.72,3045.7 h60
  text "Round" at 7388.86,3045.7 h60
  text "Top Layer - Bottom Layer" at 7764.02,3045.7 h60
  text "4" at 6161.16,2921.38 h60
  text "125.98mil (3.200mm)" at 6493.16,2921.38 h60
  text "PTH" at 7129.72,2921.38 h60
  text "Round" at 7388.86,2921.38 h60
  text "Top Layer - Bottom Layer" at 7764.02,2921.38 h60
  text "866 Total" at 6161.16,2797.06 h60
  text ".Layer_Name" at 577,-858.49 h60
M17 Embedded Cavity:
  text ".Layer_Name" at 577,-858.49 h60
M18 Embedded Assembly:
  text ".Layer_Name" at 577,-858.49 h60
M19 Embedded Keepout:
  text ".Layer_Name" at 577,-858.49 h60

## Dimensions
0,0 to 0,3000 on M2 Board Dimensions
0,0 to 3000,3000 on M2 Board Dimensions
0,-400 to 1000,-400 on M2 Board Dimensions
